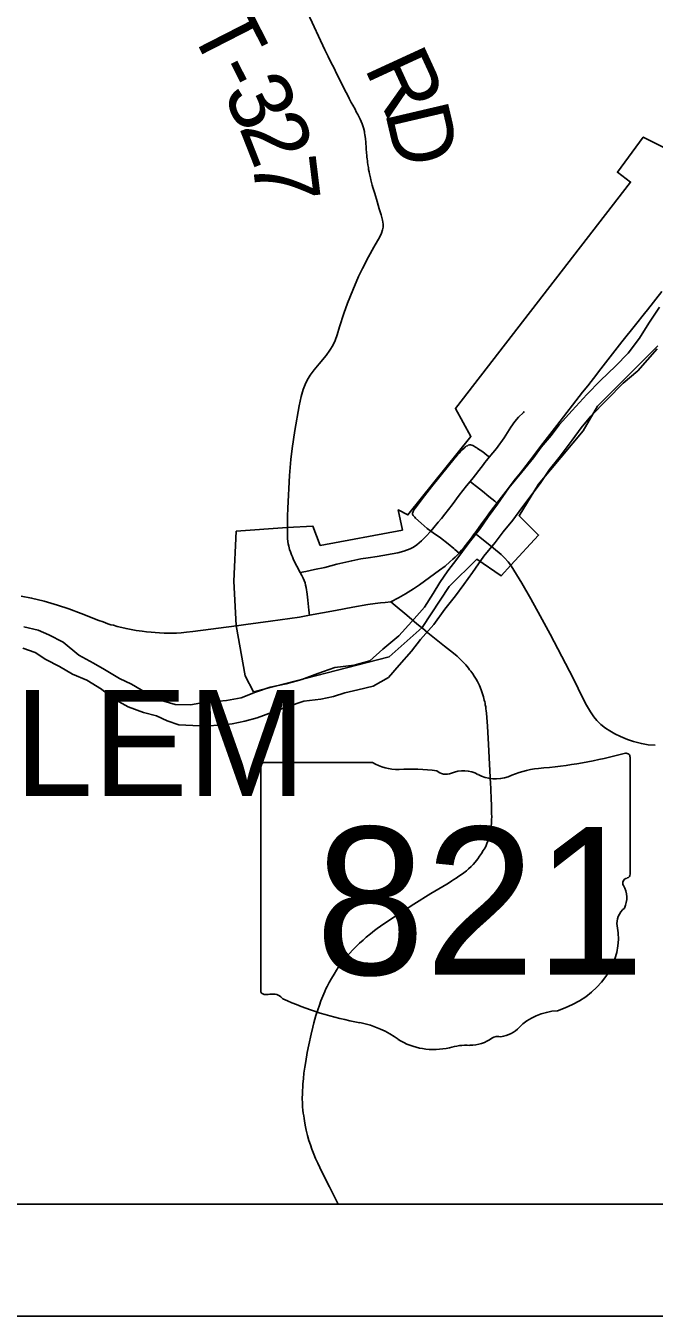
# Model space of a CAD drawing. Extents: x -10 to 158, y 8 to 33.
# Drawn here: x 128.048 to 128.609, y 24.962 to 26.114 of the extents above; entities that cross this region are included whole.
import ezdxf

# ---------------------------------------------------------------- set-up
doc = ezdxf.new("R2010")
doc.units = 0
for name, color, linetype in [('GM_X_City_Street', 7, 'Continuous'), ('GM_X_Corporation_Text', 7, 'Continuous'), ('GM_X_Major_River', 7, 'Continuous'), ('GM_X_State_Location', 7, 'Continuous'), ('GM_X_State_Route', 7, 'Continuous'), ('GM_X_State_Shield', 7, 'Continuous'), ('GM_X_Township_Road', 7, 'Continuous'), ('GM_X_Township_Road_Text', 7, 'Continuous'), ('GM_X_Township_Text', 7, 'Continuous'), ('SH_Data', 7, 'Continuous'), ('SH_Text', 7, 'Continuous')]:
    doc.layers.add(name, color=color, linetype=linetype)

msp = doc.modelspace()

# ---------------------------------------------------------------- linework, layer by layer
at = {"layer": 'GM_X_City_Street'}
for points in [[(128.2934, 25.6261), (128.2983, 25.6271), (128.3061, 25.6288), (128.3152, 25.6307), (128.326, 25.6334), (128.3393, 25.6366), (128.3473, 25.6382), (128.354, 25.6392), (128.362, 25.6404), (128.3804, 25.6437), (128.3857, 25.6452), (128.3916, 25.6473), (128.3944, 25.6487), (128.3975, 25.6508), (128.4017, 25.6544), (128.4061, 25.6588), (128.4094, 25.6625), (128.4098, 25.6631), (128.4125, 25.6664), (128.4166, 25.6711), (128.4194, 25.6744), (128.4224, 25.6783), (128.429, 25.6866), (128.4353, 25.6951), (128.4418, 25.7034), (128.445, 25.7074), (128.4476, 25.7106), (128.4548, 25.7197), (128.457, 25.7225), (128.4582, 25.7242), (128.4595, 25.726), (128.462, 25.729), (128.4653, 25.7329), (128.4685, 25.7367), (128.4754, 25.7463), (128.4814, 25.7557), (128.485, 25.7608), (128.4882, 25.7646), (128.4926, 25.769), (128.4934, 25.7699)], [(128.3937, 25.6792), (128.3941, 25.6804), (128.3944, 25.681), (128.3949, 25.682), (128.396, 25.6835), (128.4042, 25.6944), (128.4106, 25.7026), (128.4181, 25.7117), (128.4306, 25.7274), (128.4321, 25.729), (128.4338, 25.7311), (128.4351, 25.7326), (128.4365, 25.7342), (128.438, 25.7357), (128.4396, 25.7372), (128.4404, 25.7379), (128.441, 25.7384), (128.4416, 25.7388), (128.4426, 25.7393), (128.4434, 25.7397), (128.4444, 25.74), (128.4455, 25.7401), (128.4466, 25.7398), (128.4474, 25.7395), (128.4481, 25.7391), (128.4489, 25.7386), (128.4498, 25.7381), (128.4509, 25.7374), (128.4516, 25.7369), (128.4564, 25.7337), (128.4582, 25.7323), (128.4613, 25.7296), (128.462, 25.729)], [(128.445, 25.7074), (128.4469, 25.7059), (128.4507, 25.7029), (128.456, 25.6986), (128.4617, 25.694), (128.467, 25.6898), (128.469, 25.6881)], [(128.3937, 25.6792), (128.3937, 25.6781), (128.3943, 25.677), (128.3951, 25.676), (128.3956, 25.6754), (128.3963, 25.6747), (128.4012, 25.6701), (128.4068, 25.6654), (128.4098, 25.6631), (128.4121, 25.6614), (128.4185, 25.6569), (128.4253, 25.6518), (128.4305, 25.6475), (128.4314, 25.6466), (128.4352, 25.6434)]]:
    msp.add_lwpolyline(points, dxfattribs=at)
at = {"layer": 'GM_X_Major_River'}
for points in [[(128.614, 25.8628), (128.6047, 25.8486), (128.5962, 25.8352), (128.5861, 25.8218), (128.5749, 25.8103), (128.5614, 25.7976), (128.5491, 25.7849), (128.536, 25.7706), (128.5244, 25.758), (128.5174, 25.7484), (128.5084, 25.738), (128.5017, 25.7284), (128.4909, 25.7154), (128.4797, 25.7016), (128.4696, 25.687), (128.4611, 25.6759), (128.4533, 25.6644), (128.4443, 25.6529), (128.4332, 25.638), (128.425, 25.6276), (128.4179, 25.6173), (128.412, 25.6073), (128.4042, 25.5951), (128.393, 25.5824), (128.3814, 25.5697), (128.3671, 25.5578), (128.3555, 25.5474), (128.3415, 25.5434), (128.3241, 25.5412), (128.309, 25.5361), (128.2947, 25.5306), (128.2807, 25.5266), (128.2664, 25.5238), (128.2535, 25.5194), (128.2407, 25.5143), (128.2275, 25.5119), (128.207, 25.5101), (128.1953, 25.508), (128.1816, 25.5082), (128.1695, 25.5118), (128.1565, 25.5185), (128.1427, 25.5263), (128.1321, 25.5314), (128.1187, 25.5396), (128.1087, 25.5452), (128.0958, 25.5522), (128.0816, 25.5638), (128.069, 25.5704), (128.0594, 25.5745), (128.0465, 25.5777)], [(128.0456, 25.5587), (128.0567, 25.5547), (128.0662, 25.5484), (128.0785, 25.5421), (128.0899, 25.5354), (128.1029, 25.5299), (128.1159, 25.5221), (128.1258, 25.5139), (128.1396, 25.5061), (128.1533, 25.501), (128.1651, 25.4981), (128.1746, 25.4937), (128.1849, 25.49), (128.1974, 25.4894), (128.2096, 25.4892), (128.2225, 25.4898), (128.2327, 25.4911), (128.244, 25.4935), (128.255, 25.4963), (128.2686, 25.5014), (128.2818, 25.5061), (128.2965, 25.5113), (128.3116, 25.513), (128.323, 25.5154), (128.3332, 25.5186), (128.3449, 25.5214), (128.3585, 25.5246), (128.372, 25.5324), (128.3817, 25.5435), (128.3926, 25.5558), (128.4008, 25.5662), (128.4127, 25.5796), (128.4224, 25.5934), (128.4321, 25.6053), (128.4395, 25.6153), (128.447, 25.626), (128.4574, 25.6406), (128.4675, 25.6528), (128.4745, 25.6624), (128.4831, 25.6728), (128.4913, 25.6839), (128.5002, 25.6958), (128.5077, 25.7054), (128.5159, 25.718), (128.5244, 25.7288), (128.536, 25.7441), (128.5442, 25.7552), (128.5528, 25.7656), (128.5816, 25.7952), (128.5947, 25.806), (128.6033, 25.816), (128.6119, 25.8256)]]:
    msp.add_lwpolyline(points, dxfattribs=at)
at = {"layer": 'GM_X_State_Route'}
for points in [[(128.3741, 25.5998), (128.3812, 25.6036), (128.3874, 25.607), (128.3944, 25.6115), (128.3998, 25.6152), (128.4178, 25.6283), (128.4228, 25.6319), (128.427, 25.6355), (128.4297, 25.6379), (128.4316, 25.6397), (128.4352, 25.6434), (128.4373, 25.6459), (128.4397, 25.6487), (128.4431, 25.653), (128.4461, 25.6571), (128.4487, 25.6605), (128.4492, 25.6612), (128.4509, 25.6635), (128.4552, 25.6696), (128.4596, 25.6756), (128.4632, 25.6804), (128.4663, 25.6845), (128.469, 25.6881), (128.4772, 25.6988), (128.4843, 25.7081), (128.4899, 25.7152), (128.4951, 25.7217), (128.5019, 25.7306), (128.5079, 25.7385), (128.5223, 25.7572), (128.5455, 25.787), (128.5501, 25.7928), (128.5581, 25.8031), (128.5596, 25.8051), (128.568, 25.8158), (128.5805, 25.8321), (128.5926, 25.8471), (128.6007, 25.8573), (128.6034, 25.8606), (128.6163, 25.8768)], [(128.1746, 25.572), (128.1719, 25.572), (128.1677, 25.5722), (128.1638, 25.5725), (128.1602, 25.5727), (128.1562, 25.5731), (128.1523, 25.5736), (128.1469, 25.5744), (128.1424, 25.5752), (128.1378, 25.5761), (128.1341, 25.5769), (128.13, 25.578), (128.1265, 25.579), (128.1243, 25.5795), (128.1216, 25.5804), (128.1173, 25.582), (128.1134, 25.5834), (128.0977, 25.5895), (128.0867, 25.5936), (128.0767, 25.597), (128.0648, 25.6005), (128.0534, 25.6033), (128.0443, 25.6051)], [(128.3741, 25.5998), (128.3693, 25.5993), (128.3651, 25.5989), (128.3603, 25.5984), (128.3538, 25.5975), (128.3404, 25.5951), (128.3249, 25.5923), (128.3017, 25.588), (128.2926, 25.5863), (128.2668, 25.5826), (128.2448, 25.5796), (128.2364, 25.5784)], [(128.4017, 25.5769), (128.3974, 25.5804), (128.3884, 25.5879), (128.378, 25.5966), (128.3741, 25.5998)], [(128.2364, 25.5784), (128.1975, 25.5733), (128.1919, 25.5727), (128.1869, 25.5723), (128.1829, 25.5721), (128.1794, 25.5719), (128.1755, 25.572), (128.1746, 25.572)], [(128.4636, 25.3979), (128.464, 25.4022), (128.4642, 25.4054), (128.4643, 25.4083), (128.4642, 25.4108), (128.4642, 25.4132), (128.4641, 25.4163), (128.464, 25.4194), (128.4639, 25.4231), (128.4638, 25.4255), (128.4636, 25.4309), (128.4634, 25.4339), (128.4632, 25.4376), (128.4613, 25.4727), (128.4604, 25.489), (128.4595, 25.5007), (128.4593, 25.5026), (128.4591, 25.5045), (128.4589, 25.5061), (128.4585, 25.5081), (128.4583, 25.5094), (128.4581, 25.5107), (128.4577, 25.5122), (128.4574, 25.5136), (128.457, 25.5151), (128.4564, 25.5169), (128.4558, 25.5187), (128.4549, 25.5215), (128.4544, 25.5228), (128.4539, 25.5239), (128.4534, 25.5252), (128.4528, 25.5264), (128.4515, 25.5288), (128.4504, 25.5309), (128.4487, 25.5336), (128.4474, 25.5356), (128.4456, 25.5381), (128.4446, 25.5393), (128.4435, 25.5407), (128.4424, 25.5421), (128.4411, 25.5437), (128.4398, 25.5451), (128.4385, 25.5465), (128.4371, 25.5478), (128.4357, 25.5491), (128.4334, 25.5513), (128.4303, 25.554), (128.4222, 25.5605), (128.4133, 25.5676), (128.4074, 25.5723), (128.4024, 25.5763), (128.4017, 25.5769)], [(128.3273, 25.0623), (128.3194, 25.0778), (128.3126, 25.0911), (128.3107, 25.0951), (128.3089, 25.099), (128.307, 25.1032), (128.3054, 25.107), (128.3038, 25.1113), (128.3024, 25.1153), (128.3011, 25.1193), (128.2999, 25.1235), (128.2987, 25.1285), (128.2978, 25.1327), (128.297, 25.1366), (128.2967, 25.1389), (128.2964, 25.1411), (128.296, 25.1434), (128.2957, 25.1461), (128.2955, 25.1493), (128.2954, 25.1526), (128.2952, 25.1567), (128.2953, 25.161), (128.2957, 25.1694), (128.2961, 25.1745), (128.2966, 25.1793), (128.2973, 25.1846), (128.2982, 25.1898), (128.2996, 25.1976), (128.3009, 25.2044), (128.303, 25.2141), (128.3045, 25.2202), (128.3055, 25.2243), (128.3074, 25.2306), (128.3089, 25.2357), (128.3104, 25.2399), (128.3118, 25.2439), (128.3134, 25.2479), (128.3152, 25.252), (128.3163, 25.2544), (128.3173, 25.2565), (128.3192, 25.2602), (128.3211, 25.2636), (128.3236, 25.2677), (128.3257, 25.2711), (128.3273, 25.2736), (128.3292, 25.2763), (128.3316, 25.2795), (128.3342, 25.2827), (128.3358, 25.2846), (128.3375, 25.2864), (128.3401, 25.2891), (128.3434, 25.2924), (128.3463, 25.2952), (128.3494, 25.2981), (128.3523, 25.3006), (128.3561, 25.3036), (128.3597, 25.3065), (128.3621, 25.3084), (128.3649, 25.3103), (128.3724, 25.3154), (128.3775, 25.3189), (128.3947, 25.33), (128.4099, 25.3396), (128.4241, 25.348), (128.4265, 25.3495), (128.4286, 25.3508), (128.4306, 25.3522), (128.4326, 25.3534), (128.435, 25.355), (128.4374, 25.3567), (128.4393, 25.358), (128.4405, 25.3589), (128.4417, 25.3599), (128.4437, 25.3616), (128.446, 25.3638), (128.4478, 25.3655), (128.4496, 25.3676), (128.4519, 25.3706), (128.4535, 25.3728), (128.4552, 25.3753), (128.4568, 25.3779), (128.4583, 25.3805), (128.4592, 25.3824), (128.46, 25.3842), (128.461, 25.3868), (128.4617, 25.389), (128.4622, 25.3908), (128.4627, 25.3926), (128.4632, 25.3949), (128.4636, 25.3979)]]:
    msp.add_lwpolyline(points, dxfattribs=at)
at = {"layer": 'GM_X_State_Shield'}
for p, q in [((128.2582, 25.4531), (128.2582, 25.253)), ((128.358, 25.4565), (128.2614, 25.4565)), ((128.5878, 25.3568), (128.5878, 25.4615)), ((128.5877, 25.3568), (128.5878, 25.3568))]:
    msp.add_line(p, q, dxfattribs=at)
for centre, major_axis, start_param, end_param in [((128.4704, 25.7294), (0.3495, 0), 4.814394, 5.042369), ((128.5841, 25.4619), (0.00367, 0), 6.141152, 7.989035), ((128.262, 25.4535), (0.00382, 0), 1.712693, 3.28349), ((128.3809, 25.4798), (0.037, 0), 4.042523, 4.731795), ((128.3932, 25.3442), (0.133, 0), 1.404758, 1.657858), ((128.4234, 25.4546), (0.0107, 0), 3.836095, 5.185415), ((128.4391, 25.4314), (0.0222, 0), 0.950623, 2.079405), ((128.4678, 25.4632), (0.0267, 0), 4.081561, 5.145723), ((128.515, 25.3954), (0.0703, 0), 1.699011, 2.107814), ((128.5869, 25.3491), (0.00568, 0), 1.883978, 3.671073), ((128.5839, 25.3564), (0.00393, 0), 5.05454, 6.418171), ((128.5508, 25.3359), (0.0341, 0), 5.934695, 6.695948), ((128.6009, 25.313), (0.0248, 0), 2.387724, 3.262537), ((128.49, 25.2997), (0.0874, 0), 5.101752, 6.440018), ((128.262, 25.2525), (0.00385, 0), 3.00124, 4.508301), ((128.2626, 25.273), (0.0294, 0), 4.665946, 4.897461), ((128.2686, 25.2414), (0.0106, 0), 0.519207, 1.627899), ((128.4024, 25.4212), (0.2524, 0), 4.195997, 4.488961), ((128.5268, 25.1968), (0.0479, 0), 1.647645, 2.488434), ((128.3272, 25.1631), (0.079, 0), 0.823519, 1.323587), ((128.4452, 25.2255), (0.0267, 0), 4.691044, 5.507374), ((128.4694, 25.2061), (0.00752, 0), 1.147584, 2.315152), ((128.4662, 25.2336), (0.0282, 0), 4.937069, 5.64225), ((128.4126, 25.2404), (0.0501, 0), 4.026481, 4.996735), ((128.4415, 25.1712), (0.0412, 0), 1.495662, 1.94098)]:
    msp.add_ellipse(centre, major_axis=major_axis, ratio=0.8, start_param=start_param, end_param=end_param, dxfattribs=at)
at = {"layer": 'GM_X_Township_Road'}
for points in [[(128.2821, 25.6764), (128.2823, 25.6836), (128.2837, 25.7127), (128.2849, 25.7269), (128.2861, 25.7368), (128.2885, 25.7527), (128.2924, 25.7748), (128.2942, 25.7833), (128.2959, 25.7893), (128.2976, 25.7939), (128.2995, 25.7978), (128.3021, 25.8021), (128.3057, 25.8071), (128.3101, 25.8124), (128.3166, 25.8199), (128.3199, 25.8244), (128.3224, 25.8286), (128.3244, 25.8331), (128.3264, 25.8383), (128.3285, 25.8454), (128.3323, 25.8573), (128.3356, 25.8666), (128.3402, 25.8782), (128.3454, 25.8902), (128.3489, 25.8974), (128.3542, 25.9079), (128.359, 25.9165), (128.3644, 25.9256), (128.366, 25.929), (128.3669, 25.932), (128.3673, 25.9344), (128.3673, 25.9369), (128.3667, 25.9405), (128.3655, 25.9453), (128.3638, 25.9507), (128.3619, 25.9572), (128.3598, 25.9643), (128.3583, 25.9696), (128.3576, 25.9719), (128.3564, 25.9766), (128.356, 25.9783), (128.3555, 25.9807), (128.3552, 25.9818), (128.3549, 25.9836), (128.3544, 25.9859), (128.3542, 25.9876), (128.3538, 25.99), (128.3535, 25.9922), (128.3533, 25.9939), (128.3532, 25.995), (128.3529, 25.9972), (128.3527, 25.9989), (128.3526, 26), (128.3525, 26.0011), (128.3523, 26.0038), (128.3521, 26.0066), (128.3519, 26.0083), (128.3518, 26.01), (128.3516, 26.0134), (128.3511, 26.0168), (128.3508, 26.0185), (128.3506, 26.0197), (128.3498, 26.0231), (128.3487, 26.0264), (128.3478, 26.0286), (128.3469, 26.0307), (128.3448, 26.0349), (128.3434, 26.0374), (128.3423, 26.0395), (128.3403, 26.0431), (128.3389, 26.0456), (128.3383, 26.0467), (128.3369, 26.0493), (128.3351, 26.0529), (128.3343, 26.0545), (128.3332, 26.0566), (128.3325, 26.0582), (128.3281, 26.0668), (128.3259, 26.0712), (128.3254, 26.0722), (128.3238, 26.0755), (128.3205, 26.0821), (128.3182, 26.0865), (128.3152, 26.0927), (128.3, 26.1253)], [(128.282, 25.6666), (128.2819, 25.6712), (128.2821, 25.6764)], [(128.2934, 25.6261), (128.2874, 25.6375), (128.2863, 25.6401), (128.2855, 25.642), (128.2845, 25.6446), (128.2838, 25.6467), (128.2831, 25.6497), (128.2826, 25.6518), (128.2824, 25.6539), (128.2821, 25.6564), (128.282, 25.6588), (128.2819, 25.6611), (128.282, 25.6631), (128.282, 25.6656), (128.282, 25.6666)], [(128.4812, 25.6328), (128.4791, 25.6355), (128.4757, 25.6392), (128.4726, 25.6422), (128.4659, 25.6477), (128.4538, 25.6575), (128.4492, 25.6612)], [(128.3017, 25.588), (128.3011, 25.5926), (128.3001, 25.6015), (128.2995, 25.6067), (128.2993, 25.6087), (128.299, 25.6106), (128.2986, 25.6127), (128.2981, 25.6148), (128.2976, 25.6168), (128.2969, 25.6189), (128.2959, 25.621), (128.2949, 25.6233), (128.2934, 25.6261)], [(128.6103, 25.4719), (128.6041, 25.4724), (128.598, 25.4734), (128.5908, 25.4753), (128.5855, 25.4771), (128.5792, 25.4797), (128.5742, 25.4822), (128.5699, 25.4847), (128.5659, 25.4871), (128.5618, 25.4903), (128.5581, 25.4939), (128.5554, 25.4974), (128.5525, 25.5017), (128.5489, 25.5078), (128.5457, 25.5139), (128.5414, 25.5227), (128.5392, 25.5275), (128.5338, 25.538), (128.5164, 25.571), (128.5076, 25.5874), (128.4992, 25.6027), (128.4913, 25.6167), (128.4817, 25.6321), (128.4812, 25.6328)]]:
    msp.add_lwpolyline(points, dxfattribs=at)
at = {"layer": 'GM_X_Township_Text'}
msp.add_lwpolyline([(128.6125, 25.8284), (128.5588, 25.7747), (128.546, 25.7524), (128.5061, 25.705), (128.4887, 25.6767), (128.5061, 25.6595), (128.4815, 25.6326), (128.4726, 25.623), (128.451, 25.6379), (128.4263, 25.6135), (128.4022, 25.5769), (128.3727, 25.5509), (128.2517, 25.5197), (128.2441, 25.534), (128.2362, 25.5789), (128.2341, 25.6184), (128.2362, 25.6629), (128.2818, 25.6662), (128.3047, 25.6674), (128.3112, 25.6503), (128.3845, 25.664), (128.3808, 25.682), (128.3895, 25.6775), (128.4457, 25.7474), (128.4319, 25.7724), (128.5883, 25.9746), (128.5765, 25.9833), (128.5996, 26.0147), (128.6829, 25.9728)], dxfattribs=at)
at = {"layer": 'SH_Data'}
for p, q in [((126.1038, 25.0623), (132.9038, 25.0623)), ((126.0038, 24.9623), (133.0038, 24.9623))]:
    msp.add_line(p, q, dxfattribs=at)
at = {"layer": 'SH_Text'}
msp.add_lwpolyline([(126.1038, 27.0364), (126.1038, 25.0623), (130.4362, 25.0623)], dxfattribs=at)

# ---------------------------------------------------------------- texts
at = {"layer": 'GM_X_Corporation_Text'}
msp.add_text('LOWER SALEM', height=0.094697, rotation=0, dxfattribs=at).set_placement((127.3695, 25.4266))
at = {"layer": 'GM_X_State_Location'}
for s in ['s', 'r']:
    msp.add_text(s, height=0.000189, dxfattribs=at).set_placement((128.4193, 25.3397))
msp.add_text('821', height=0.000189, rotation=0, dxfattribs=at).set_placement((128.3524, 25.326))
at = {"layer": 'GM_X_State_Shield'}
msp.add_text('821', height=0.13184, dxfattribs=at).set_placement((128.3068, 25.2671))
at = {"layer": 'GM_X_Township_Road_Text'}
for s, rotation, p in [('T', 297.0845, (128.1938, 26.1124)), ('R', 294.7111, (128.3501, 26.0769)), ('-', 296.8583, (128.2132, 26.0746)), ('3', 295.9041, (128.2236, 26.054)), ('D', 283.1898, (128.3687, 26.0374)), ('2', 291.4874, (128.2384, 26.0236)), ('7', 276.9643, (128.2503, 25.9947))]:
    msp.add_text(s, height=0.0568, rotation=rotation, dxfattribs=at).set_placement(p)

doc.saveas('drawing.dxf')
